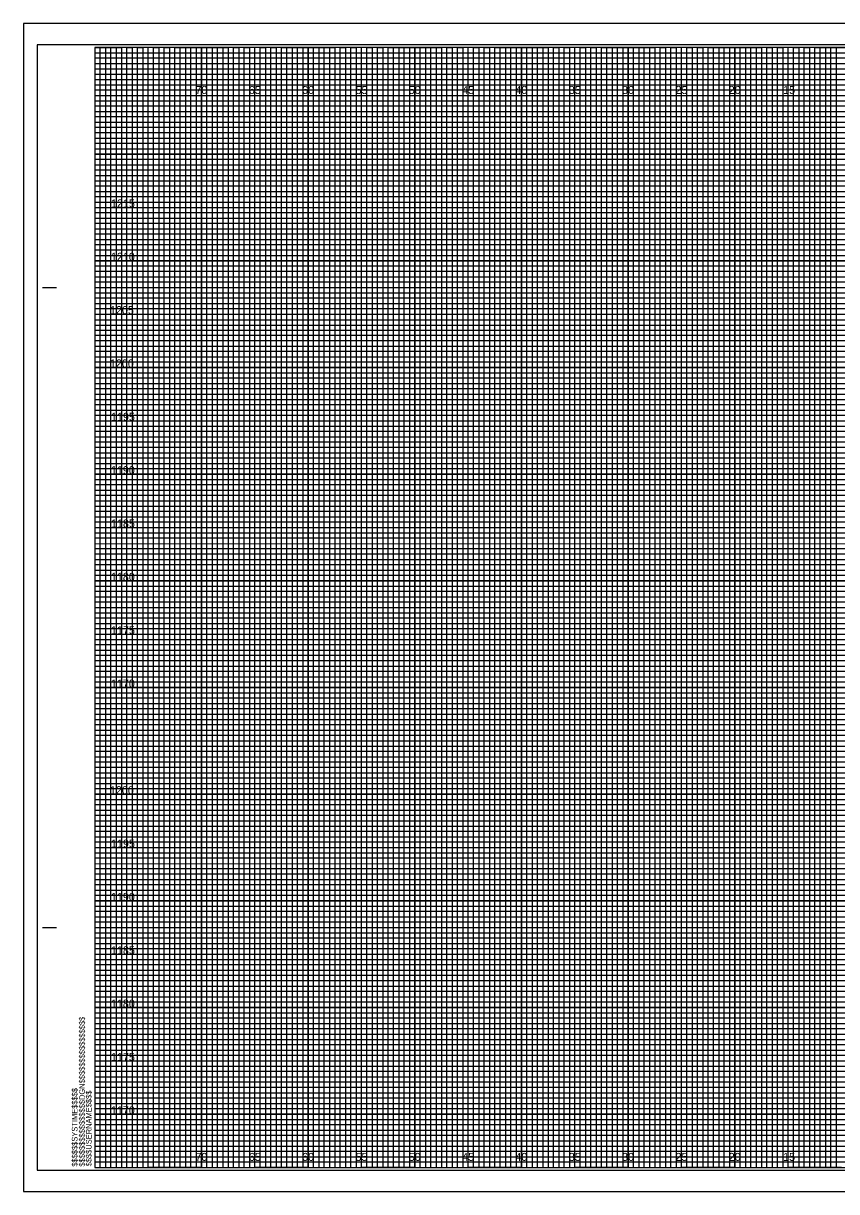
# Model space of a CAD drawing. Extents: x 3478 to 3647, y -9 to 1255.
# Drawn here: x 3478.3 to 3554.6, y -9.3 to 100.2 of the extents above; entities that cross this region are included whole.
import ezdxf

# ---------------------------------------------------------------- set-up
doc = ezdxf.new("R2010")
doc.units = 0
for name, color, linetype in [('Exist Cross Section Cell', 7, 'Continuous'), ('Prop CMT Subgrade Earthwork', 7, 'Continuous'), ('Prop Conc 4in Sidewalk', 7, 'Continuous'), ('Prop Conc Island Cover', 7, 'Continuous'), ('Sheet Cross Section CELL', 7, 'Continuous'), ('Sheet Cross Section Grid Minor 1 CELL', 7, 'Continuous'), ('Sheet Cross Section Grid Minor 2 CELL', 7, 'Continuous'), ('Sheet Cutting Line CELL', 7, 'Continuous'), ('Sheet DOT Grid CELL', 7, 'Continuous'), ('Sheet Plot Border Inside CELL', 7, 'Continuous')]:
    doc.layers.add(name, color=color, linetype=linetype)

msp = doc.modelspace()

# ---------------------------------------------------------------- linework, layer by layer
at = {"layer": 'Exist Cross Section Cell'}
for points in [[(3485.01, 97.97), (3487.51, 97.97), (3487.51, -7.03), (3492.51, -7.03), (3492.51, 97.97), (3497.51, 97.97), (3497.51, -7.03), (3502.51, -7.03), (3502.51, 97.97), (3507.51, 97.97), (3507.51, -7.03), (3512.51, -7.03), (3512.51, 97.97), (3517.51, 97.97), (3517.51, -7.03), (3522.51, -7.03), (3522.51, 97.97), (3527.51, 97.97), (3527.51, -7.03), (3532.51, -7.03), (3532.51, 97.97), (3537.51, 97.97), (3537.51, -7.03), (3542.51, -7.03), (3542.51, 97.97), (3547.51, 97.97), (3547.51, -7.03), (3552.51, -7.03), (3552.51, 97.97), (3557.51, 97.97)], [(3485.01, 95.47), (3622.51, 95.47)], [(3485.01, 85.47), (3645.01, 85.47), (3645.01, 90.47), (3485.01, 90.47)], [(3485.01, 75.47), (3645.01, 75.47), (3645.01, 80.47), (3485.01, 80.47)], [(3485.01, 65.47), (3645.01, 65.47), (3645.01, 70.47), (3485.01, 70.47)], [(3485.01, 55.47), (3645.01, 55.47), (3645.01, 60.47), (3485.01, 60.47)], [(3485.01, 45.47), (3645.01, 45.47), (3645.01, 50.47), (3485.01, 50.47)], [(3485.01, 35.47), (3645.01, 35.47), (3645.01, 40.47), (3485.01, 40.47)], [(3485.01, 25.47), (3645.01, 25.47), (3645.01, 30.47), (3485.01, 30.47)], [(3485.01, 15.47), (3645.01, 15.47), (3645.01, 20.47), (3485.01, 20.47)], [(3485.01, 5.47), (3645.01, 5.47), (3645.01, 10.47), (3485.01, 10.47)], [(3485.01, -4.53), (3645.01, -4.53), (3645.01, 0.47), (3485.01, 0.47)]]:
    msp.add_lwpolyline(points, dxfattribs=at)
at = {"layer": 'Prop CMT Subgrade Earthwork'}
msp.add_lwpolyline([(3478.31, -9.28), (3646.66, -9.28), (3646.66, 100.22), (3478.31, 100.22)], close=True, dxfattribs=at)
at = {"layer": 'Prop Conc 4in Sidewalk'}
for p, q in [((3490.01, 97.97), (3485.01, 97.97)), ((3490.01, -7.03), (3490.01, 97.97)), ((3500.01, 97.97), (3495.01, 97.97)), ((3495.01, 97.97), (3495.01, -7.03)), ((3500.01, -7.03), (3500.01, 97.97)), ((3510.01, 97.97), (3505.01, 97.97)), ((3505.01, 97.97), (3505.01, -7.03)), ((3510.01, -7.03), (3510.01, 97.97)), ((3520.01, 97.97), (3515.01, 97.97)), ((3515.01, 97.97), (3515.01, -7.03)), ((3520.01, -7.03), (3520.01, 97.97)), ((3530.01, 97.97), (3525.01, 97.97)), ((3525.01, 97.97), (3525.01, -7.03)), ((3530.01, -7.03), (3530.01, 97.97)), ((3540.01, 97.97), (3535.01, 97.97)), ((3535.01, 97.97), (3535.01, -7.03)), ((3540.01, -7.03), (3540.01, 97.97)), ((3550.01, 97.97), (3545.01, 97.97)), ((3545.01, 97.97), (3545.01, -7.03)), ((3550.01, -7.03), (3550.01, 97.97)), ((3495.01, -7.03), (3490.01, -7.03)), ((3505.01, -7.03), (3500.01, -7.03)), ((3515.01, -7.03), (3510.01, -7.03)), ((3525.01, -7.03), (3520.01, -7.03)), ((3535.01, -7.03), (3530.01, -7.03)), ((3545.01, -7.03), (3540.01, -7.03)), ((3555.01, -7.03), (3550.01, -7.03))]:
    msp.add_line(p, q, dxfattribs=at)
for points in [[(3485.01, 92.97), (3645.01, 92.97), (3645.01, 87.97), (3485.01, 87.97)], [(3485.01, 82.97), (3645.01, 82.97), (3645.01, 77.97), (3485.01, 77.97)], [(3485.01, 72.97), (3645.01, 72.97), (3645.01, 67.97), (3485.01, 67.97)], [(3485.01, 62.97), (3645.01, 62.97), (3645.01, 57.97), (3485.01, 57.97)], [(3485.01, 52.97), (3645.01, 52.97), (3645.01, 47.97), (3485.01, 47.97)], [(3485.01, 42.97), (3645.01, 42.97), (3645.01, 37.97), (3485.01, 37.97)], [(3485.01, 32.97), (3645.01, 32.97), (3645.01, 27.97), (3485.01, 27.97)], [(3485.01, 22.97), (3645.01, 22.97), (3645.01, 17.97), (3485.01, 17.97)], [(3485.01, 12.97), (3645.01, 12.97), (3645.01, 7.97), (3485.01, 7.97)], [(3485.01, 2.97), (3645.01, 2.97), (3645.01, -2.03), (3485.01, -2.03)]]:
    msp.add_lwpolyline(points, dxfattribs=at)
at = {"layer": 'Sheet Cross Section CELL'}
for p, q in [((3480.11, 75.47), (3481.36, 75.47)), ((3480.16, 75.47), (3481.41, 75.47)), ((3480.11, 15.47), (3481.36, 15.47)), ((3480.16, 15.47), (3481.41, 15.47))]:
    msp.add_line(p, q, dxfattribs=at)
msp.add_lwpolyline([(3645.01, 97.97), (3485.01, 97.97), (3485.01, -7.03), (3645.01, -7.03)], close=True, dxfattribs=at)
at = {"layer": 'Sheet Cross Section Grid Minor 1 CELL'}
for p, q in [((3485.01, 97.47), (3615.01, 97.47)), ((3615.01, 96.96), (3485.01, 96.96)), ((3485.01, 96.96), (3485.01, 96.47)), ((3485.01, 96.47), (3615.01, 96.47)), ((3615.01, 95.92), (3485.01, 95.92)), ((3485.01, 95.92), (3485.01, 94.97)), ((3485.01, 94.97), (3645.01, 94.97))]:
    msp.add_line(p, q, dxfattribs=at)
for points in [[(3485.01, 94.47), (3620.01, 94.47), (3645.01, 94.47), (3645.01, 93.97), (3485.01, 93.97)], [(3485.01, 93.47), (3645.01, 93.47), (3645.01, 92.47), (3485.01, 92.47)], [(3485.01, 91.97), (3645.01, 91.97), (3645.01, 91.47), (3485.01, 91.46)], [(3485.01, 90.97), (3645.01, 90.97), (3645.01, 89.97), (3485.01, 89.97)], [(3485.01, 89.47), (3645.01, 89.47), (3645.01, 88.97), (3485.01, 88.97)], [(3485.01, 88.47), (3645.01, 88.47), (3645.01, 87.47), (3485.01, 87.47)], [(3485.01, 86.97), (3645.01, 86.97), (3645.01, 86.47), (3485.01, 86.47)], [(3485.01, 85.97), (3645.01, 85.97), (3645.01, 84.97), (3485.01, 84.97)], [(3485.01, 84.47), (3645.01, 84.47), (3645.01, 83.97), (3485.01, 83.97)], [(3485.01, 83.47), (3645.01, 83.47), (3645.01, 82.47), (3485.01, 82.47)], [(3485.01, 81.97), (3645.01, 81.97), (3645.01, 81.47), (3485.01, 81.47)], [(3485.01, 80.97), (3645.01, 80.97), (3645.01, 79.95), (3645.01, 79.47), (3645.01, 78.97), (3485.01, 78.97)], [(3485.01, 79.97), (3645.01, 79.97), (3645.01, 79.47), (3485.01, 79.47)], [(3485.01, 78.47), (3645.01, 78.47), (3645.01, 77.47), (3485.01, 77.49)], [(3485.01, 77.49), (3645.01, 77.47), (3645.01, 76.97), (3485.01, 76.97)], [(3485.01, 76.47), (3645.01, 76.47), (3645.01, 75.97), (3485.01, 75.97)], [(3485.01, 74.97), (3645.01, 74.97), (3645.01, 74.47), (3485.01, 74.47)], [(3485.01, 73.97), (3645.01, 73.97), (3645.01, 73.47), (3485.01, 73.47)], [(3484.97, 72.42), (3645.01, 72.42), (3645.01, 71.91), (3484.97, 71.91)], [(3485.01, 71.47), (3645.01, 71.47), (3645.01, 70.97), (3485.01, 70.97)], [(3485.01, 69.97), (3645.01, 69.97), (3645.01, 69.47), (3485.01, 69.47)], [(3485.01, 68.97), (3645.01, 68.97), (3645.01, 68.47), (3485.01, 68.47)], [(3485.01, 67.47), (3645.01, 67.47), (3645.01, 66.97), (3485.01, 66.97)], [(3485.01, 66.47), (3645.01, 66.47), (3645.01, 65.97), (3485.01, 65.97)], [(3485.01, 64.97), (3645.01, 64.97), (3645.01, 64.47), (3485.01, 64.47)], [(3485.01, 63.97), (3645.01, 63.97), (3645.01, 63.47), (3485.01, 63.47)], [(3485.01, 62.47), (3645.01, 62.47), (3645, 61.96), (3485.01, 61.97)], [(3485.01, 61.47), (3645.01, 61.47), (3645.01, 60.97), (3485.01, 60.97)], [(3485.01, 59.97), (3645.01, 59.97), (3645.01, 59.47), (3485.01, 59.47)], [(3485.01, 58.97), (3645.01, 58.97), (3645.01, 58.47), (3485.01, 58.47)], [(3485.01, 57.47), (3645.01, 57.47), (3645.01, 56.97), (3485.01, 56.97)], [(3485.01, 56.47), (3645.01, 56.47), (3645.01, 55.97), (3485.01, 55.97)], [(3485.01, 54.97), (3645.01, 54.97), (3645.01, 54.47), (3485.01, 54.47)], [(3485.01, 53.97), (3645.01, 53.97), (3645.01, 53.47), (3485.01, 53.47)], [(3485.01, 52.47), (3645.01, 52.47), (3645.01, 51.97), (3485.01, 51.97)], [(3485.01, 51.47), (3645.04, 51.43), (3645.01, 50.97), (3485.01, 50.97)], [(3485.01, 49.97), (3645.01, 49.97), (3645.01, 49.47), (3485.01, 49.47)], [(3485.01, 48.97), (3645.01, 48.97), (3645.01, 48.47), (3485.01, 48.47)], [(3485.01, 47.47), (3645.01, 47.47), (3645.01, 46.97), (3485.01, 46.97)], [(3485.01, 46.47), (3645.01, 46.47), (3645.01, 45.97), (3485.01, 45.97)], [(3485.01, 44.97), (3645.01, 44.97), (3645.01, 44.47), (3485.01, 44.47)], [(3485.01, 43.97), (3645.01, 43.97), (3645.01, 43.47), (3485.01, 43.47)], [(3485.01, 42.47), (3645.01, 42.47), (3645.01, 41.97), (3485.01, 41.97)], [(3485.01, 41.47), (3645.01, 41.47), (3645.01, 40.97), (3485.01, 40.97)], [(3485.01, 39.97), (3645.01, 39.97), (3645.01, 39.47), (3485.01, 39.47)], [(3485.01, 38.97), (3645.01, 38.97), (3645.01, 38.47), (3485.01, 38.47)], [(3485.01, 37.47), (3645.01, 37.47), (3645.01, 36.97), (3485.01, 36.97)], [(3485.01, 36.47), (3645.01, 36.47), (3645.01, 35.97), (3485.01, 35.97)], [(3485.01, 34.97), (3645.01, 34.97), (3645.01, 34.47), (3485.01, 34.47)], [(3485.01, 33.97), (3645.01, 33.97), (3645.01, 33.47), (3485.01, 33.47)], [(3485.01, 32.47), (3645.01, 32.47), (3645, 31.96), (3485.01, 31.97)], [(3485.01, 31.47), (3645.01, 31.47), (3645.01, 30.97), (3485.01, 30.97)], [(3485.01, 29.97), (3645.01, 29.97), (3645.01, 29.47), (3485.01, 29.47)], [(3485.01, 28.97), (3645.01, 28.97), (3645.01, 28.47), (3485.01, 28.47)], [(3485.01, 27.47), (3645.01, 27.47), (3645.01, 26.97), (3485.01, 26.97)], [(3485.01, 26.47), (3645.01, 26.47), (3645.01, 25.97), (3485.01, 25.97)], [(3485.01, 24.97), (3645.01, 24.97), (3645.01, 24.47), (3485.01, 24.47)], [(3485.01, 23.97), (3645.01, 23.97), (3645.01, 23.47), (3485.01, 23.47)], [(3485.01, 22.47), (3645.01, 22.47), (3645.01, 21.97), (3485.01, 21.97)], [(3485.01, 21.47), (3645.04, 21.43), (3645.01, 20.97), (3485.01, 20.97)], [(3485.01, 19.97), (3645.01, 19.97), (3645.01, 19.47), (3485.01, 19.47)], [(3485.01, 18.97), (3645.01, 18.97), (3645.01, 18.47), (3485.01, 18.47)], [(3485.01, 17.47), (3645.01, 17.47), (3645.01, 16.97), (3485.01, 16.97)], [(3485.01, 16.47), (3645.01, 16.47), (3645.01, 15.97), (3485.01, 15.97)], [(3485.01, 14.97), (3645.01, 14.97), (3645.01, 14.47), (3485.01, 14.47)], [(3485.01, 13.97), (3645.01, 13.97), (3645.01, 13.47), (3485.01, 13.47)], [(3485.01, 12.47), (3645.01, 12.47), (3645.01, 11.97), (3485.01, 11.97)], [(3485.01, 11.47), (3645.01, 11.47), (3645.01, 10.97), (3485.01, 10.97)], [(3485.01, 9.97), (3645.01, 9.97), (3645.01, 9.47), (3485.01, 9.47)], [(3485.01, 8.97), (3645.01, 8.97), (3645.01, 8.47), (3485.01, 8.47)], [(3485.01, 7.47), (3645.01, 7.47), (3645.01, 6.97), (3485.01, 6.97)], [(3485.01, 6.47), (3645.01, 6.47), (3645.01, 5.97), (3485.01, 5.97)], [(3485.01, 4.97), (3645.01, 4.97), (3645.01, 4.47), (3485.01, 4.47)], [(3485.01, 3.97), (3645.01, 3.97), (3645.01, 3.47), (3485.01, 3.47)], [(3485.01, 2.47), (3645.01, 2.47), (3645.01, 1.97), (3485.01, 1.97)], [(3485.01, 1.47), (3645.01, 1.47), (3645.01, 0.97), (3485.01, 0.97)], [(3485.01, -0.03), (3645.01, -0.03), (3645.01, -0.53), (3485.01, -0.53)], [(3485.01, -1.03), (3645.01, -1.03), (3645.01, -1.53), (3485.01, -1.53)], [(3485.01, -2.53), (3645.01, -2.53), (3645.01, -3.03), (3485.01, -3.03)], [(3485.01, -3.53), (3645.01, -3.53), (3645.01, -4.03), (3485.01, -4.03)], [(3485.01, -5.03), (3645.01, -5.03), (3645.01, -5.53), (3485.01, -5.53)], [(3485.01, -6.03), (3645.01, -6.03), (3645.01, -6.53), (3485.01, -6.53)]]:
    msp.add_lwpolyline(points, dxfattribs=at)
at = {"layer": 'Sheet Cross Section Grid Minor 2 CELL'}
for points in [[(3485.01, -7.03), (3485.51, -7.03), (3485.51, 97.97), (3486.01, 97.97), (3486.01, -7.03)], [(3486.01, -7.03), (3486.51, -7.03), (3486.51, 97.97), (3487.01, 97.97), (3487.01, -7.03)], [(3487.51, -7.03), (3488.01, -7.03), (3488.01, 97.97), (3488.51, 97.97), (3488.51, -7.03)], [(3488.51, -7.03), (3489.01, -7.03), (3489.01, 97.97), (3489.51, 97.97), (3489.51, -7.03)], [(3490.01, -7.03), (3490.51, -7.03), (3490.51, 97.97), (3491.01, 97.97), (3491.01, -7.03)], [(3491.01, -7.03), (3491.51, -7.03), (3491.51, 97.97), (3492.01, 97.97), (3492.01, -7.03)], [(3492.51, -7.03), (3493.01, -7.03), (3493.01, 97.97), (3493.51, 97.97), (3493.51, -7.03)], [(3493.51, -7.03), (3494.01, -7.03), (3494.01, 97.97), (3494.51, 97.97), (3494.51, -7.03)], [(3495.01, -7.03), (3495.51, -7.03), (3495.51, 97.97), (3496.01, 97.97), (3496.01, -7.03)], [(3496.01, -7.03), (3496.51, -7.03), (3496.51, 97.97), (3497.01, 97.97), (3497.01, -7.03)], [(3497.51, -7.03), (3498.01, -7.03), (3498.01, 97.97), (3498.51, 97.97), (3498.51, -7.03)], [(3498.51, -7.03), (3499.01, -7.03), (3499.01, 97.97), (3499.51, 97.97), (3499.51, -7.03)], [(3500.01, -7.03), (3500.51, -7.03), (3500.51, 97.97), (3501.01, 97.97), (3501.01, -7.03)], [(3501.01, -7.03), (3501.51, -7.03), (3501.51, 97.97), (3502.01, 97.97), (3502.01, -7.03)], [(3502.51, -7.03), (3503.01, -7.03), (3503.01, 97.97), (3503.51, 97.97), (3503.51, -7.03)], [(3503.51, -7.03), (3504.01, -7.03), (3504.01, 97.97), (3504.51, 97.97), (3504.51, -7.03)], [(3505.01, -7.03), (3505.51, -7.03), (3505.51, 97.97), (3506.01, 97.97), (3506.01, -7.03)], [(3506.01, -7.03), (3506.51, -7.03), (3506.51, 97.97), (3507.01, 97.97), (3507.01, -7.03)], [(3507.51, -7.03), (3508.01, -7.03), (3508.01, 97.97), (3508.51, 97.97), (3508.51, -7.03)], [(3508.51, -7.03), (3509.01, -7.03), (3509.01, 97.97), (3509.51, 97.97), (3509.51, -7.03)], [(3510.01, -7.03), (3510.51, -7.03), (3510.51, 97.97), (3511.01, 97.97), (3511.01, -7.03)], [(3511.01, -7.03), (3511.51, -7.03), (3511.51, 97.97), (3512.01, 97.97), (3512.01, -7.03)], [(3512.51, -7.03), (3513.01, -7.03), (3513.01, 97.97), (3513.51, 97.97), (3513.51, -7.03)], [(3513.51, -7.03), (3514.01, -7.03), (3514.01, 97.97), (3514.51, 97.97), (3514.51, -7.03)], [(3515.01, -7.03), (3515.51, -7.03), (3515.51, 97.97), (3516.01, 97.97), (3516.01, -7.03)], [(3516.01, -7.03), (3516.51, -7.03), (3516.51, 97.97), (3517.01, 97.97), (3517.01, -7.03)], [(3517.51, -7.03), (3518.01, -7.03), (3518.01, 97.97), (3518.51, 97.97), (3518.51, -7.03)], [(3518.51, -7.03), (3519.01, -7.03), (3519.01, 97.97), (3519.51, 97.97), (3519.51, -7.03)], [(3520.01, -7.03), (3520.51, -7.03), (3520.51, 97.97), (3521.01, 97.97), (3521.01, -7.03)], [(3521.01, -7.03), (3521.51, -7.03), (3521.51, 97.97), (3522.01, 97.97), (3522.01, -7.03)], [(3522.51, -7.03), (3523.01, -7.03), (3523.01, 97.97), (3523.51, 97.97), (3523.51, -7.03)], [(3523.51, -7.03), (3524.01, -7.03), (3524.01, 97.97), (3524.51, 97.97), (3524.51, -7.03)], [(3525.01, -7.03), (3525.51, -7.03), (3525.51, 97.97), (3526.01, 97.97), (3526.01, -7.03)], [(3526.01, -7.03), (3526.51, -7.03), (3526.51, 97.97), (3527.01, 97.97), (3527.01, -7.03)], [(3527.51, -7.03), (3528.01, -7.03), (3528.01, 97.97), (3528.51, 97.97), (3528.51, -7.03)], [(3528.51, -7.03), (3529.01, -7.03), (3529.01, 97.97), (3529.51, 97.97), (3529.51, -7.03)], [(3530.01, -7.03), (3530.51, -7.03), (3530.51, 97.97), (3531.01, 97.97), (3531.01, -7.03)], [(3531.01, -7.03), (3531.51, -7.03), (3531.51, 97.97), (3532.01, 97.97), (3532.01, -7.03)], [(3532.51, -7.03), (3533.01, -7.03), (3533.01, 97.97), (3533.51, 97.97), (3533.51, -7.03)], [(3533.51, -7.03), (3534.01, -7.03), (3534.01, 97.97), (3534.51, 97.97), (3534.51, -7.03)], [(3535.01, -7.03), (3535.51, -7.03), (3535.51, 97.97), (3536.01, 97.97), (3536.01, -7.03)], [(3536.01, -7.03), (3536.51, -7.03), (3536.51, 97.97), (3537.01, 97.97), (3537.01, -7.03)], [(3537.51, -7.03), (3538.01, -7.03), (3538.01, 97.97), (3538.51, 97.97), (3538.51, -7.03)], [(3538.51, -7.03), (3539.01, -7.03), (3539.01, 97.97), (3539.51, 97.97), (3539.51, -7.03)], [(3540.01, -7.03), (3540.51, -7.03), (3540.51, 97.97), (3541.01, 97.97), (3541.01, -7.03)], [(3541.01, -7.03), (3541.51, -7.03), (3541.51, 97.97), (3542.01, 97.97), (3542.01, -7.03)], [(3542.51, -7.03), (3543.01, -7.03), (3543.01, 97.97), (3543.51, 97.97), (3543.51, -7.03)], [(3543.51, -7.03), (3544.01, -7.03), (3544.01, 97.97), (3544.51, 97.97), (3544.51, -7.03)], [(3545.01, -7.03), (3545.51, -7.03), (3545.51, 97.97), (3546.01, 97.97), (3546.01, -7.03)], [(3546.01, -7.03), (3546.51, -7.03), (3546.51, 97.97), (3547.01, 97.97), (3547.01, -7.03)], [(3547.51, -7.03), (3548.01, -7.03), (3548.01, 97.97), (3548.51, 97.97), (3548.51, -7.03)], [(3548.51, -7.03), (3549.01, -7.03), (3549.01, 97.97), (3549.51, 97.97), (3549.51, -7.03)], [(3550.01, -7.03), (3550.51, -7.03), (3550.51, 97.97), (3551.01, 97.97), (3551.01, -7.03)], [(3551.01, -7.03), (3551.51, -7.03), (3551.51, 97.97), (3552.01, 97.97), (3552.01, -7.03)], [(3552.51, -7.03), (3553.01, -7.03), (3553.01, 97.97), (3553.51, 97.97), (3553.51, -7.03)], [(3553.51, -7.03), (3554.01, -7.03), (3554.01, 97.97), (3554.51, 97.97), (3554.51, -7.03)]]:
    msp.add_lwpolyline(points, dxfattribs=at)
at = {"layer": 'Sheet Cutting Line CELL'}
for p, q in [((3646.66, 100.22), (3478.31, 100.22)), ((3478.31, 100.22), (3478.31, -9.28)), ((3478.31, -9.28), (3646.66, -9.28))]:
    msp.add_line(p, q, dxfattribs=at)
at = {"layer": 'Sheet DOT Grid CELL'}
for p, q in [((3490.01, -7.03), (3490.01, 97.97)), ((3495.01, -7.03), (3495.01, 97.97)), ((3500.01, -7.03), (3500.01, 97.97)), ((3505.01, -7.03), (3505.01, 97.97)), ((3510.01, -7.03), (3510.01, 97.97)), ((3515.01, -7.03), (3515.01, 97.97)), ((3520.01, -7.03), (3520.01, 97.97)), ((3525.01, -7.03), (3525.01, 97.97)), ((3530.01, -7.03), (3530.01, 97.97)), ((3535.01, -7.03), (3535.01, 97.97)), ((3540.01, -7.03), (3540.01, 97.97)), ((3545.01, -7.03), (3545.01, 97.97)), ((3550.01, -7.03), (3550.01, 97.97)), ((3485.01, 92.97), (3645.01, 92.97)), ((3485.01, 87.97), (3645.01, 87.97)), ((3485.01, 82.97), (3645.01, 82.97)), ((3485.01, 77.97), (3645.01, 77.97)), ((3485.01, 72.97), (3645.01, 72.97)), ((3485.01, 67.97), (3645.01, 67.97)), ((3485.01, 62.97), (3645.01, 62.97)), ((3485.01, 57.97), (3645.01, 57.97)), ((3485.01, 52.97), (3645.01, 52.97)), ((3485.01, 47.97), (3645.01, 47.97)), ((3485.01, 42.97), (3645.01, 42.97)), ((3485.01, 37.97), (3645.01, 37.97)), ((3485.01, 32.97), (3645.01, 32.97)), ((3485.01, 27.97), (3645.01, 27.97)), ((3485.01, 22.97), (3645.01, 22.97)), ((3485.01, 17.97), (3645.01, 17.97)), ((3485.01, 12.97), (3645.01, 12.97)), ((3485.01, 7.97), (3645.01, 7.97)), ((3485.01, 2.97), (3645.01, 2.97)), ((3485.01, -2.03), (3645.01, -2.03))]:
    msp.add_line(p, q, dxfattribs=at)
at = {"layer": 'Sheet Plot Border Inside CELL'}
msp.add_lwpolyline([(3479.61, -7.28), (3646.21, -7.28), (3646.21, 98.22), (3479.61, 98.22)], close=True, dxfattribs=at)

# ---------------------------------------------------------------- texts
at = {"layer": 'Prop Conc Island Cover'}
for s, p in [('70', (3494.44, 93.6)), ('65', (3499.45, 93.6)), ('60', (3504.44, 93.6)), ('55', (3509.45, 93.6)), ('50', (3514.44, 93.6)), ('45', (3519.45, 93.6)), ('40', (3524.44, 93.6)), ('35', (3529.45, 93.6)), ('30', (3534.44, 93.6)), ('25', (3539.45, 93.6)), ('20', (3544.44, 93.6)), ('15', (3549.54, 93.6)), ('1215', (3486.53, 82.97)), ('1210', (3486.52, 77.97)), ('1205', (3486.44, 72.97)), ('1200', (3486.43, 67.97)), ('1195', (3486.53, 62.97)), ('1190', (3486.52, 57.97)), ('1185', (3486.53, 52.97)), ('1180', (3486.52, 47.97)), ('1175', (3486.53, 42.97)), ('1170', (3486.52, 37.97)), ('1200', (3486.43, 27.97)), ('1195', (3486.53, 22.97)), ('1190', (3486.52, 17.97)), ('1185', (3486.53, 12.97)), ('1180', (3486.52, 7.97)), ('1175', (3486.53, 2.97)), ('1170', (3486.52, -2.03)), ('70', (3494.44, -6.4)), ('65', (3499.45, -6.4)), ('60', (3504.44, -6.4)), ('55', (3509.45, -6.4)), ('50', (3514.44, -6.4)), ('45', (3519.45, -6.4)), ('40', (3524.44, -6.4)), ('35', (3529.45, -6.4)), ('30', (3534.44, -6.4)), ('25', (3539.45, -6.4)), ('20', (3544.44, -6.4)), ('15', (3549.54, -6.4))]:
    msp.add_text(s, height=0.75, dxfattribs=at).set_placement(p)
at = {"layer": 'Sheet Cross Section CELL'}
for s, p in [('$$$$$$$$$$$$$$$$DGN$$$$$$$$$$$$$$$$', (3484.07, -6.94)), ('$$$$$$SYSTIME$$$$$', (3483.38, -6.94)), ('$$$$USERNAME$$$$', (3484.7, -6.91))]:
    msp.add_text(s, height=0.525, rotation=90, dxfattribs=at).set_placement(p)

doc.saveas('drawing.dxf')
